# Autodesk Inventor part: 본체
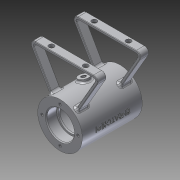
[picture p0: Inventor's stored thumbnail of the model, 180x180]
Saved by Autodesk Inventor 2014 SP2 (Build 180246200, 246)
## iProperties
Created: 2016-03
Part Number: 본체
Material: 알루미늄 6061
Document SubType Name: Modeling
Designer: 703
Density: 2.71 g/cm^3
Appearance: 알루미늄 - 평지
Mass: 213.146 g
Surface Area: 333.935 cm^2
Volume: 78.6516 cm^3
Author: 703
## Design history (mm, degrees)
sketch "스케치1"
  geometry: 1 further point
sketch "스케치2"
  geometry: C1 r 26 at (0, 0); 1 further point
  constraints: 1 centre point
  dimensions: "d0" = 52 diameter of C1
extrude "돌출1" new body sketch "스케치2" stored distance "d1" = 70; taper "d2" = 0 deg
sketch "스케치3"
  geometry: C1 r 16 at (0, 0)
  constraints: 1 centre point
  dimensions: "d3" = 32 diameter of C1
extrude "돌출2" cut sketch "스케치3" distance "d4" = 12; taper "d5" = 0 deg
sketch "스케치4"
  geometry: C1 r 21 at (0, 0); 1 further point
  constraints: 1 centre point
  dimensions: "d6" = 42 diameter of C1
extrude "돌출3" cut sketch "스케치4" stored distance "d7" = 42; taper "d8" = 0 deg
sketch "스케치5"
  geometry: C1 r 14 at (0, 0)
  constraints: 1 centre point
  dimensions: "d9" = 28 diameter of C1
extrude "돌출4" cut sketch "스케치5" distance "d10" = 10; taper "d11" = 0 deg
sketch "스케치6"
  geometry: C1 r 16 at (0, 0)
  constraints: 1 centre point
  dimensions: "d12" = 32 diameter of C1
extrude "돌출5" cut sketch "스케치6" distance "d13" = 12; taper "d14" = 0 deg
sketch "스케치7"
  geometry: C1 r 14 at (0, 0)
  constraints: 1 centre point
  dimensions: "d15" = 28 diameter of C1
extrude "돌출6" cut sketch "스케치7" distance "d16" = 12; taper "d17" = 0 deg
sketch "스케치8"
  geometry: C1 r 21 at (0, 0); 4 further points
  constraints: 1 centre point
  dimensions: "d18" = 42 diameter of C1
hole "구멍1" sketch "스케치8" at (0, 20.989), (20.973, 0), (0, -21), (-20.998, 0) diameter "d19" = 3.242; stored, may be unused: countersink angle "d23" = 90 deg, drill point angle "d25" = 118 deg; dims "d20" = 8, "d21" = 4, "d22" = 2, "d24" = 10
node "작업 평면2"
  node "작업 평면1"
sketch "스케치9"
  geometry: C1 r 5 at (0, 0); 1 further point
  constraints: 1 centre point
  dimensions: "d27" = 10 diameter of C1
extrude "돌출7" join sketch "스케치9" stored distance "d28" = 12; taper "d29" = 0 deg
node "작업 평면4"
sketch "스케치14"
  geometry: L1 (42.594, 65)-(-42.594, 65); L2 (-15.407, 17.911)-(-42.594, 65); L3 (-16.613, 20)-(45.415, 20); L4 (15.407, 17.911)-(42.594, 65); L5 (12.994, 19.732)-(37.398, 62); L6 (37.398, 62)-(0, 62); L7 (-12.994, 19.732)-(-37.398, 62); L8 (-37.398, 62)-(0, 62); C1 r 26 at (0, 0) reference; C2 r 26 at (0, 0); A1 r 23.626 centre (0, 0) between (15.407, 17.911) and (12.577, 20); A2 r 23.626 centre (0, 0) between (-12.577, 20) and (-15.407, 17.911); 2 further points
  constraints: 16 end point, 6 point on circle, 3 centre point, 3 point on line, 1 horizontal, 1 midpoint, 1 vertical alignment
  dimensions: "d51" = 65 distance from line of point (0, 0) L1; "d54" = 120 deg angle of L3 L2; "d55" = 3 distance between parallel lines of L4 L5; "d56" = 3 distance between parallel lines of L1 L6
extrude "돌출9" join sketch "스케치14" distance "d57" = 10; taper "d58" = 0 deg
sketch "스케치15"
  geometry: L1 (0, 0)-(85.188, 0) reference; L2 (93.836, 5)-(-8.648, 5); L3 (42.594, 5)-(42.594, 13.621); L4 (62.594, 21.917)-(62.594, -11.131); C1 r 3 at (62.594, 5); C2 r 3 at (22.594, 5); 2 further points
  constraints: 6 end point, 2 centre point, 1 midpoint, 1 symmetric about line, 1 vertical alignment, 1 other
  dimensions: "d59" = 5 distance between parallel lines of L1 L2; "d60" = 20 distance between parallel lines of L3 L4; "d61" = 6 diameter of C1
extrude "돌출10" cut sketch "스케치15" distance "d62" = 10; taper "d63" = 0 deg
node "작업 평면5"
sketch "스케치16"
  geometry: L1 (19.102, -7.182)-(-18.331, -7.182); L2 (-18.331, -7.182)-(-18.331, 7.6); L3 (-18.331, 7.6)-(19.102, 7.6); L4 (19.102, 7.6)-(19.102, -7.182); 1 further point
  constraints: 2 other
feature "엠보싱1" sketch "스케치16" dims "d64" = 0.5, "d65" = 0
sketch "스케치17"
  geometry: L1 (0, 0)-(7.506, 28.012); L2 (0, 0)-(29, 0); 1 further point
  constraints: 4 end point, 1 equal length, 1 horizontal
  dimensions: "d66" = 29 distance of L1.start L1.end; "d67" = 75 deg angle of L2 L1
node "작업 평면6"
sketch "스케치18"
  geometry: C1 r 6 at (0, 0); 1 further point
  constraints: 1 centre point
  dimensions: "d68" = 12 diameter of C1
extrude "돌출11" join sketch "스케치18" stored distance "d69" = 10; taper "d70" = 0 deg
sketch "스케치19"
  geometry: 1 further point
hole "구멍4" sketch "스케치19" at (0, 0) diameter "d71" = 5.188; stored, may be unused: countersink angle "d75" = 90 deg, drill point angle "d77" = 118 deg; dims "d72" = 15, "d73" = 4, "d74" = 2, "d76" = 15
sketch "스케치20"
  geometry: 1 further point
hole "구멍5" sketch "스케치20" at (0, 0) diameter "d78" = 5.188; stored, may be unused: countersink angle "d82" = 90 deg, drill point angle "d84" = 118 deg; dims "d79" = 15, "d80" = 4, "d81" = 2, "d83" = 15
fillet "모깎기5" dims "d97" = 5, "d98" = 2, "d99" = 2, "d100" = 0.3, "d106" = 3
fillet "모깎기6" dims "d101" = 3, "d102" = 0.5
chamfer "모따기2" distance "d103" = 1; stored, may be unused: second distance "d104" = 2, angle "d105" = 45 deg
node "솔리드1"
mirror "대칭1"
mirror "대칭2"
other parameters: "d26" = -3
